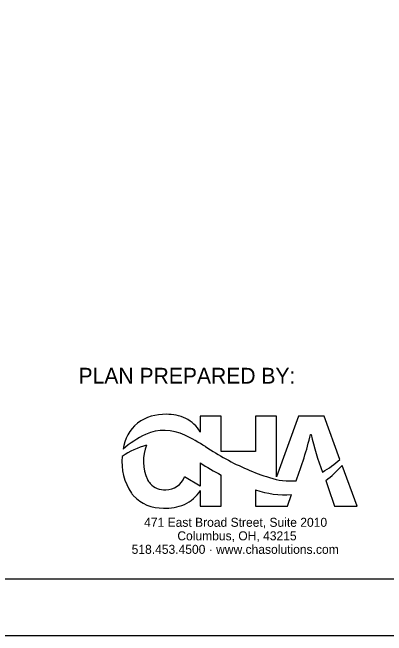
# Model space of a CAD drawing. Extents: x 0 to 44, y -23.8 to 22.
# Drawn here: x 6.63 to 9.95, y 0 to 5.53 of the extents above; entities that cross this region are included whole.
import ezdxf

# ---------------------------------------------------------------- set-up
doc = ezdxf.new("R2010")
doc.units = 0
for name, color, linetype in [('Default', 7, 'Continuous'), ('SH_Border', 7, 'Continuous'), ('SH_Cut_Line', 7, 'Continuous'), ('SH_Text', 7, 'Continuous')]:
    doc.layers.add(name, color=color, linetype=linetype)

msp = doc.modelspace()

# ---------------------------------------------------------------- linework, layer by layer
at = {"layer": 'Default'}
msp.add_line((9.2761, 1.7867), (9.2816, 1.7867), dxfattribs=at)
for points in [[(9.5359, 1.5641), (9.3957, 1.9484), (9.1675, 1.9484), (8.9729, 1.4102), (8.9729, 1.9484), (8.7882, 1.9484), (8.7882, 1.6346), (8.4812, 1.6346), (8.4812, 1.9484), (8.2965, 1.9484), (8.2965, 1.8075)], [(8.2965, 1.5333), (8.2965, 1.3257), (8.1574, 1.4092)], [(9.4097, 1.3755), (9.431, 1.3154), (9.4894, 1.1484), (9.6877, 1.1484), (9.5555, 1.5104)], [(8.2965, 1.2879), (8.2965, 1.1484), (8.4812, 1.1484), (8.4812, 1.4258)], [(8.7882, 1.2949), (8.7882, 1.1484), (8.8782, 1.1484), (8.9729, 1.1484), (9.071, 1.1484), (9.1062, 1.2514)]]:
    msp.add_lwpolyline(points, dxfattribs=at)
for centre, radius, start, end in [((7.9808, 1.5555), 0.4094, 88.0817, 126.0325), ((8.0029, 1.576), 0.3887, 64.9016, 91.2438), ((7.9713, 1.6075), 0.3625, 129.6629, 172.5664), ((8.0286, 1.6505), 0.3105, 30.3756, 63.3712), ((8.1544, 1.0464), 0.8149, 114.8364, 131.7457), ((7.9782, 1.4206), 0.4013, 63.1724, 114.4396), ((7.5102, 0.3804), 1.5416, 57.2913, 65.1), ((5.7396, 2.6603), 3.6428, 339.3263, 346.125), ((11.2888, 2.2102), 2.0515, 191.9132, 201.6837), ((8.025, 0.967), 0.7527, 105.7483, 123.9538), ((8.1762, 1.5471), 0.3837, 157.8882, 204.8663), ((10.3281, 4.7492), 3.6571, 237.1308, 240.4227), ((8.0864, 1.5381), 0.4847, 173.6843, 214.2778), ((9.551, 3.4387), 2.134, 241.1998, 252.5446), ((8.8973, 2.2786), 0.9583, 300.42, 311.7894), ((9.6078, 3.5734), 2.4252, 237.2686, 242.3197), ((8.7872, 2.1951), 1.0292, 307.219, 318.2934), ((7.9516, 1.443), 0.1362, 204.8663, 223.055), ((7.9928, 1.4709), 0.1759, 269.2163, 339.4439), ((9.1021, 1.9887), 0.6162, 251.9229, 274.261), ((7.9794, 1.469), 0.1743, 223.055, 273.5972), ((8.0256, 1.4553), 0.3185, 294.1165, 328.289), ((9.0497, 2.0218), 0.7725, 250.2087, 274.1935), ((7.8384, 1.3691), 0.1846, 214.2778, 222.6269), ((7.9583, 1.4794), 0.3475, 222.6269, 271.9347), ((7.9888, 1.5704), 0.4387, 267.5421, 292.3552)]:
    msp.add_arc(centre, radius, start, end, dxfattribs=at)
at = {"layer": 'SH_Border'}
msp.add_lwpolyline([(1.5, 21.5), (33.5, 21.5), (33.5, 0.5), (1.5, 0.5)], close=True, dxfattribs=at)
at = {"layer": 'SH_Cut_Line'}
msp.add_lwpolyline([(0, 0), (34, 0), (34, 22), (0, 22)], close=True, dxfattribs=at)

# ---------------------------------------------------------------- texts
at = {"layer": 'Default'}
for s, p in [('471 East Broad Street, Suite 2010', (7.7988, 0.9656)), ('Columbus, OH, 43215', (8.0934, 0.8456)), ('518.453.4500 · www.chasolutions.com', (7.6879, 0.7256))]:
    msp.add_text(s, height=0.08, dxfattribs=at).set_placement(p)
at = {"layer": 'SH_Text'}
msp.add_text('PLAN PREPARED BY:', height=0.14, dxfattribs=at).set_placement((7.2164, 2.2377))

doc.saveas('drawing.dxf')
